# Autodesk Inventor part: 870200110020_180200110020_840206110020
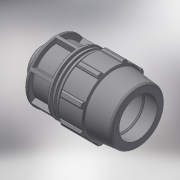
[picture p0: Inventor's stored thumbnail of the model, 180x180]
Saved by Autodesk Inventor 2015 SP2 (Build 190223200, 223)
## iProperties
Created: 2017-02
Part Number: 870200110020_180200110020_840206110020
Material: Generic
Description: PLASSON MALE ADAPTOR 110-2"
Document SubType Name: Modeling
Designer: KIM
Mass: 964.158 g
Surface Area: 1468.9 cm^2
Volume: 964.158 cm^3
Density: 1 g/cm^3
Appearance: Default
Author: KIM
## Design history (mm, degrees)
derived "87020.ipt"
feature "Solid1::87020.ipt"
tag "TaggingFeature1"
body "Solid1"
other parameters: "d4" = 37.57143, "d5" = 65.75, "d7" = 181, "d8" = 135.75, "d9" = 37.57143, "d11" = 7.51429, "d12" = 144.8, "d13" = 120 deg, "d14" = 143, "d15" = 6 deg, "d16" = 162.9, "d18" = 5.5, "d19" = 35 deg, "d20" = 17.5 deg, "d21" = 168.33, "d23" = 0, "d25" = 360 deg, "d27" = 3.62, "d34" = 9.05, "d36" = 0, "d42" = 65.75, "d43" = 5.43, "d46" = 3.3, "d49" = 215, "d51" = 263, "d52" = 26, "d53" = 2.2, "d55" = 360 deg, "d57" = 59.614, "d58" = 41.7298, "d59" = 52.6, "d61" = 159.642, "d62" = 7.57429, "d63" = 7.57429, "d66" = 15.14857, "E_" = 181, "H_" = 263, "l_" = 215, "l_2" = 26, "R_" = 59.614, "d60" = 37.87143
